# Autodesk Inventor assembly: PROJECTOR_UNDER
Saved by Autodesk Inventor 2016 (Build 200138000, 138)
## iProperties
Created: 2015-11
Part Number: PROJECTOR_UNDER
Document SubType Name: Assembly
Designer: John
Author: John
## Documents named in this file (5)
- D:\3D Printer Designs\John Ledden Designs\DLP Printer\V0-4\PROJECTOR_UNDER.iam
- D:\3D Printer Designs\John Ledden Designs\DLP Printer\V0-4\Frame_Back_ProjUnder.ipt
- D:\3D Printer Designs\John Ledden Designs\DLP Printer\V0-4\Base_Under.ipt
- D:\3D Printer Designs\John Ledden Designs\DLP Printer\V0-4\Leg_Under.ipt
- D:\3D Printer Designs\John Ledden Designs\DLP Printer\V0-4\Acer_Projector.ipt
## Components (7 placed, 7 different names)
1. Frame_Back_ProjUnder_1001
2. Base_Under_1002
3. Leg_Under_1003
4. Acer_Projector_1004
5. Leg_Under_1005
6. Leg_Under_1006
7. Leg_Under_1007
